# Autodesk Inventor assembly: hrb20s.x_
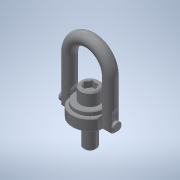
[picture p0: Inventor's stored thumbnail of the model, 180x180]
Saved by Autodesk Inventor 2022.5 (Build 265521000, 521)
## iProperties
Part Number: hrb20s.x_
Material: 一般
Document SubType Name: Assembly
Designer: ImaoCorp
Sending System: SOLIDWORKS 2017-2017317
MC: AMD64
MC_MODEL: Intel64 Family 6 Model 60 Stepping 3, GenuineIntel
OS: Windows_NT
FRU: Parasolid Version 29.0, build 201,  4-17-2017
FORMAT: text
GUISE: transmit
KEY: hrb20s
FILE: hrb20s.x_t
DATE: Mon Jul 01 17:38:57 2019
Author: ImaoCorp
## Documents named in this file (3)
- X:\14_SW2022-Inv2022\00_全2023-1023新製品(TCC)まで\h\hrb20s\HRB20S.iam
- X:\14_SW2022-Inv2022\00_全2023-1023新製品(TCC)まで\h\hrb20s\hrb20s_01.ipt
- X:\14_SW2022-Inv2022\00_全2023-1023新製品(TCC)まで\h\hrb20s\hrb20s_02.ipt
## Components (2 placed, 2 different names)
1. hrb20s_01
2. hrb20s_02
